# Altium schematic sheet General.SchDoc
size A; SheetNumber: 1; SheetTotal: 4
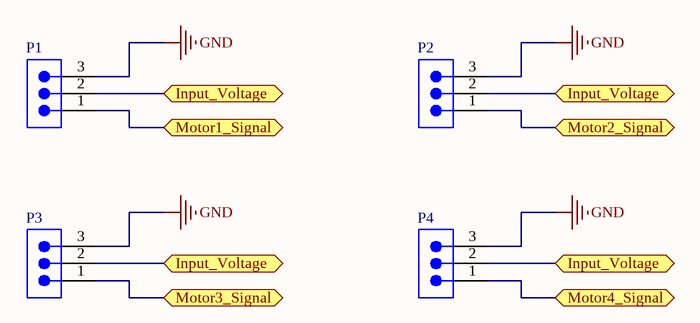
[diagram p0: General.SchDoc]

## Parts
P1  M1  [61900311121]  (value not drawn)
P2  M2  [61900311121]  (value not drawn)
P3  M3  [61900311121]  (value not drawn)
P4  M4  [61900311121]  (value not drawn)

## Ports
Input_Voltage (bidir, see General[2B], General[2C], General[3B], Microcontroller[1A]), Input_Voltage (bidir, see General[2B], General[2C], General[3C], Microcontroller[1A]), Input_Voltage (bidir, see General[2B], General[3B], General[3C], Microcontroller[1A]), Input_Voltage (bidir, see General[2C], General[3B], General[3C], Microcontroller[1A]), Motor1_Signal (bidir, see Microcontroller[4B]), Motor2_Signal (bidir, see Microcontroller[4B]), Motor3_Signal (bidir, see Microcontroller[4B]), Motor4_Signal (bidir, see Microcontroller[4B])

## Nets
GND: P1.3 P2.3 P3.3 P4.3
Input_Voltage: P1.2 P2.2 P3.2 P4.2 ; port Input_Voltage
Motor1_Signal: P1.1 ; port Motor1_Signal
Motor2_Signal: P2.1 ; port Motor2_Signal
Motor3_Signal: P3.1 ; port Motor3_Signal
Motor4_Signal: P4.1 ; port Motor4_Signal

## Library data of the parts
P1-P4 = CMP-1502-00585-2: NexarPartId: 18818222; Current Rating: 3A; Voltage Rating: 250V; Number of Positions: 3; Insulation Resistance: 1GΩ; Gender: Male; Pitch: 2.54mm; Connector Type: Male Pin; Contact Resistance: 20mΩ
